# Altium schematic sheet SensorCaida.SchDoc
size A4
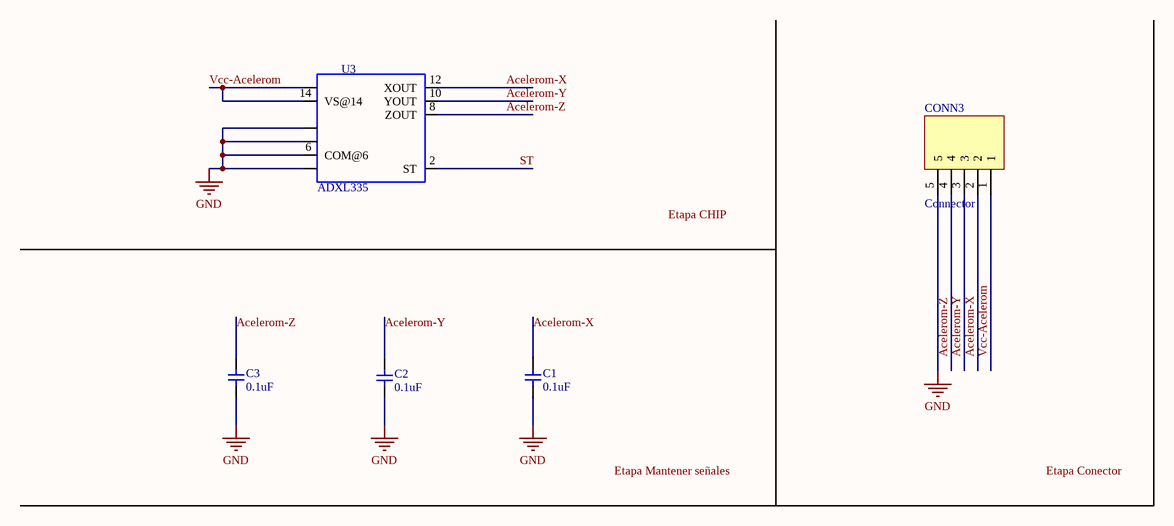
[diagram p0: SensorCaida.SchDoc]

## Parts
C1  value 0.1uF  [C1206-1.00]  (hidden comment: C)
C2  value 0.1uF  [C1206-1.00]  (hidden comment: C)
C3  value 0.1uF  [C1206-1.00]  (hidden comment: C)
CONN3  Connector  [1x5x2.54 Pin Header TH V]
U3  ADXL335  [*LFCSP-16]

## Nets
GND: C2.2 C3.2 CONN3.5 U3.3(COM@3) U3.5(COM@5) U3.6(COM@6) U3.7(COM@7)
Acelerom-X: C1.1 CONN3.2 U3.12(XOUT)
Acelerom-Y: CONN3.3 U3.10(YOUT)
Acelerom-Z: C3.1 CONN3.4 U3.8(ZOUT)
ST: U3.2(ST)
Vcc-Acelerom: CONN3.1 U3.14(VS@14) U3.15(VS@15)

Not connected (* = marked no-connect by the designer): C1 2; C2 1

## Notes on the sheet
- Labels drawn without touching a wire or pin: Etapa CHIP, Etapa Conector, Etapa Mantener señales

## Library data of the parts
C1-C3 = C: Capacitor, generic
CONN3 = Header 1x5
U3 = ADXL335: AcelerÃ³metro X, Y, Eje Z Â± 3g 1.6kHz _X, Y_, 550Hz _Z_ 16-LFCSP-LQ _4x4_; MF: Analog Devices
